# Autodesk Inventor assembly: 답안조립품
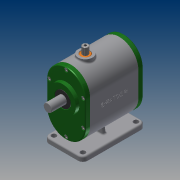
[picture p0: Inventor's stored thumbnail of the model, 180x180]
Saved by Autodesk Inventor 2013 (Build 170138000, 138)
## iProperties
Created: 2016-12
Part Number: 답안조립품
Document SubType Name: Assembly
Designer: Administrator
Mass: 2543.94 g
Surface Area: 2007.05 cm^2
Volume: 724.781 cm^3
Density: 3.50995 g/cm^3
Author: Administrator
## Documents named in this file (14)
- C:\Users\Administrator\Desktop\361208V1009\답안조립품.iam
- C:\Users\Administrator\Desktop\361208V1009\본체.ipt
- C:\Users\Administrator\Desktop\361208V1009\가변스프링.ipt
- C:\Users\Administrator\Desktop\361208V1009\뒤커버.ipt
- C:\Users\Administrator\Desktop\361208V1009\메인축.ipt
- C:\Users\Administrator\Desktop\361208V1009\베어링 608.ipt
- C:\Users\Administrator\Desktop\361208V1009\베어링 6003.ipt
- C:\Users\Administrator\Desktop\361208V1009\볼트 M4.ipt
- C:\Users\Administrator\Desktop\361208V1009\부시.ipt
- C:\Users\Administrator\Desktop\361208V1009\서브축.ipt
- C:\Users\Administrator\Desktop\361208V1009\슬라이더.ipt
- C:\Users\Administrator\Desktop\361208V1009\앞커버.ipt
- C:\Users\Administrator\Desktop\361208V1009\오일실 8 22 7.ipt
- C:\Users\Administrator\Desktop\361208V1009\오일실 17 32 8.ipt
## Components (1 placed, 1 different names)
1. 가변스프링:1
